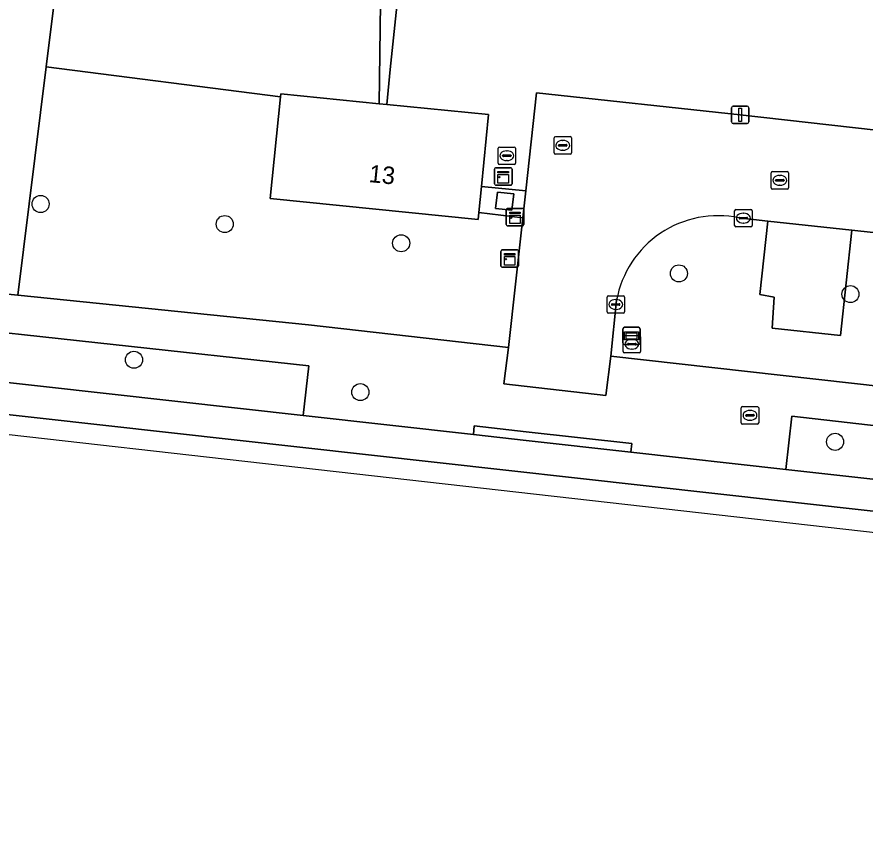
# Model space of a CAD drawing. Extents: x 162510 to 163918, y 388494 to 389774.
# Drawn here: x 162970.81 to 163019.44, y 388523.13 to 388570.84 of the extents above; entities that cross this region are included whole.
import ezdxf

# ---------------------------------------------------------------- set-up
doc = ezdxf.new("R2010")
doc.units = 0
for name, color, linetype in [('IMGEO_Berm_groen', 7, 'Continuous'), ('IMGEO_Boom', 7, 'Continuous'), ('IMGEO_Brandkraan', 7, 'Continuous'), ('IMGEO_Erf', 7, 'Continuous'), ('IMGEO_Groenvoorziening', 7, 'Continuous'), ('IMGEO_Hek', 7, 'Continuous'), ('IMGEO_Kast', 7, 'Continuous'), ('IMGEO_Kolk', 7, 'Continuous'), ('IMGEO_Lage_trafo', 7, 'Continuous'), ('IMGEO_Lichtmast', 7, 'Continuous'), ('IMGEO_Loofbos', 7, 'Continuous'), ('IMGEO_Pand', 7, 'Continuous'), ('IMGEO_Pand_nummerreeks', 7, 'Continuous'), ('IMGEO_Rijbaan_lokaal_gesloten', 7, 'Continuous'), ('IMGEO_Rijbaan_lokaal_open', 7, 'Continuous'), ('IMGEO_Rioolput', 7, 'Continuous'), ('IMGEO_Terreindeel_open', 7, 'Continuous'), ('IMGEO_Verklikker', 7, 'Continuous'), ('IMGEO_Voetpad_onverhard', 7, 'Continuous'), ('IMGEO_Voetpad_open', 7, 'Continuous')]:
    doc.layers.add(name, color=color, linetype=linetype)

msp = doc.modelspace()

# ---------------------------------------------------------------- linework, layer by layer
at = {"layer": 'IMGEO_Berm_groen'}
msp.add_lwpolyline([(163015.252, 388547.952), (163014.91, 388544.896), (163040.394, 388542.064), (163040.636, 388545.038)], close=True, dxfattribs=at)
at = {"layer": 'IMGEO_Boom'}
for centre in [(162972.163, 388560.113), (162982.721, 388558.962), (162992.839, 388557.86), (163008.769, 388556.133), (163018.606, 388554.944), (162977.517, 388551.18), (162990.498, 388549.326), (163017.725, 388546.476)]:
    msp.add_circle(centre, 0.489, dxfattribs=at)
at = {"layer": 'IMGEO_Brandkraan'}
for p, q in [((163005.57, 388551.648), (163005.57, 388552.5)), ((163005.645, 388552.574), (163006.497, 388552.574)), ((163005.872, 388552.117), (163006.27, 388552.117)), ((163006.058, 388552.354), (163006.083, 388552.354)), ((163006.571, 388552.5), (163006.571, 388551.648)), ((163005.829, 388552.068), (163005.829, 388552.08)), ((163006.267, 388552.031), (163005.869, 388552.031)), ((163006.081, 388551.794), (163006.056, 388551.794)), ((163006.313, 388552.08), (163006.313, 388552.068)), ((163006.497, 388551.574), (163005.645, 388551.574))]:
    msp.add_line(p, q, dxfattribs=at)
for points in [[(163005.57, 388551.648), (163005.57, 388552.5)], [(163005.645, 388552.574), (163006.497, 388552.574)], [(163006.571, 388552.5), (163006.571, 388551.648)], [(163006.497, 388551.574), (163005.645, 388551.574)]]:
    msp.add_lwpolyline(points, dxfattribs=at)
for centre, radius, start, end in [((163005.647, 388552.498), 0.0765, 91.552, 178.448), ((163005.647, 388552.498), 0.0765, 91.552, 178.448), ((163005.869, 388552.077), 0.0403, 85.8775, 175.7526), ((163006.274, 388552.079), 0.0386, 1.7309, 96.639), ((163006.495, 388552.498), 0.0765, 1.552, 88.448), ((163006.495, 388552.498), 0.0765, 1.552, 88.448), ((163005.647, 388551.65), 0.0765, 181.552, 268.448), ((163005.647, 388551.65), 0.0765, 181.552, 268.448), ((163005.866, 388552.067), 0.0366, 178.938, 274.7102), ((163006.27, 388552.074), 0.043, 264.8664, 352.4533), ((163006.495, 388551.65), 0.0765, 271.552, 358.448), ((163006.495, 388551.65), 0.0765, 271.552, 358.448)]:
    msp.add_arc(centre, radius, start, end, dxfattribs=at)
for centre, major_axis, ratio, start_param, end_param in [((163006.057, 388552.074), (-0.387, 0.002), 0.722429, 4.712389, 7.853982), ((163006.082, 388552.074), (-0.39, 0.002), 0.717154, 1.570796, 4.712389)]:
    msp.add_ellipse(centre, major_axis=major_axis, ratio=ratio, start_param=start_param, end_param=end_param, dxfattribs=at)
at = {"layer": 'IMGEO_Erf'}
msp.add_lwpolyline([(162992.946, 388574.941), (162992.203, 388567.817), (162992.026, 388565.819), (162997.858, 388565.235), (162997.448, 388561.109), (162999.987, 388560.86), (163000.607, 388566.496), (163012.283, 388565.224), (163023.98, 388563.913)], dxfattribs=at)
at = {"layer": 'IMGEO_Groenvoorziening'}
for points in [[(162992.946, 388574.941), (162992.355, 388574.994), (162992.829, 388580.29), (162993.498, 388580.23), (162993.73, 388582.932), (162994.196, 388586.945), (162994.478, 388589.486), (163002.555, 388588.59), (163003.829, 388588.448), (163004.733, 388595.939), (163002.79, 388596.108), (163000, 388596.356), (162992.929, 388596.983), (162991.826, 388584.623), (162991.571, 388565.865), (162992.026, 388565.819), (162992.203, 388567.817)], [(162999.817, 388559.316), (162997.301, 388559.633), (162997.261, 388559.233), (162985.319, 388560.432), (162985.926, 388566.254), (162972.488, 388567.987), (162970.86, 388554.877), (162987.529, 388553.178), (162998.998, 388551.886)], [(162987.228, 388547.98), (162987.546, 388550.825), (162965.086, 388553.284), (162964.782, 388550.488)]]:
    msp.add_lwpolyline(points, close=True, dxfattribs=at)
for points in [[(163047.561, 388555.463), (163018.69, 388558.618), (163018.036, 388552.566), (163014.124, 388552.987), (163014.233, 388554.771), (163013.404, 388554.928), (163013.862, 388559.137), (163012.22, 388559.314)], [(163005.197, 388554.592), (163004.856, 388551.379), (163026.503, 388548.968), (163052.421, 388546.115), (163052.668, 388548.774)]]:
    msp.add_lwpolyline(points, dxfattribs=at)
msp.add_arc((163011.007, 388553.534), 5.906, 78.1511, 169.6797, dxfattribs=at)
at = {"layer": 'IMGEO_Hek'}
for points in [[(163005.069, 388617.81), (163001.65, 388618.175), (163000, 388618.351), (162979.016, 388620.588), (162976.424, 388599.705), (162974.828, 388586.841), (162972.488, 388567.987)], [(162972.488, 388567.987), (162970.86, 388554.877)]]:
    msp.add_lwpolyline(points, dxfattribs=at)
at = {"layer": 'IMGEO_Kast'}
for p, q in [((162998.198, 388561.264), (162998.198, 388562.105)), ((162998.198, 388562.105), (162998.198, 388561.264)), ((162998.273, 388562.189), (162999.114, 388562.189)), ((162999.114, 388562.189), (162998.273, 388562.189)), ((162999.198, 388562.114), (162999.198, 388561.273)), ((162999.198, 388561.273), (162999.198, 388562.114)), ((162999.123, 388561.189), (162998.282, 388561.189)), ((162998.282, 388561.189), (162999.123, 388561.189)), ((162998.868, 388558.936), (162998.868, 388559.777)), ((162998.868, 388559.777), (162998.868, 388558.936)), ((162998.943, 388559.861), (162999.784, 388559.861)), ((162999.784, 388559.861), (162998.943, 388559.861)), ((162999.868, 388559.786), (162999.868, 388558.945)), ((162999.868, 388558.945), (162999.868, 388559.786)), ((162999.793, 388558.861), (162998.952, 388558.861)), ((162998.952, 388558.861), (162999.793, 388558.861)), ((162998.638, 388557.482), (162999.479, 388557.482)), ((162999.479, 388557.482), (162998.638, 388557.482)), ((162998.563, 388556.557), (162998.563, 388557.398)), ((162998.563, 388557.398), (162998.563, 388556.557)), ((162999.563, 388557.407), (162999.563, 388556.566)), ((162999.563, 388556.566), (162999.563, 388557.407)), ((162999.488, 388556.482), (162998.647, 388556.482)), ((162998.647, 388556.482), (162999.488, 388556.482))]:
    msp.add_line(p, q, dxfattribs=at)
for points in [[(162998.393, 388561.979), (162998.993, 388561.979), (162998.993, 388561.894), (162998.393, 388561.894), (162998.393, 388561.979)], [(162998.393, 388561.804), (162998.993, 388561.804), (162998.993, 388561.315), (162998.393, 388561.315), (162998.393, 388561.804)], [(162999.063, 388559.651), (162999.663, 388559.651), (162999.663, 388559.566), (162999.063, 388559.566), (162999.063, 388559.651)], [(162999.063, 388559.476), (162999.663, 388559.476), (162999.663, 388558.987), (162999.063, 388558.987), (162999.063, 388559.476)], [(162998.758, 388557.272), (162999.358, 388557.272), (162999.358, 388557.187), (162998.758, 388557.187), (162998.758, 388557.272)], [(162998.758, 388557.097), (162999.358, 388557.097), (162999.358, 388556.608), (162998.758, 388556.608), (162998.758, 388557.097)]]:
    msp.add_lwpolyline(points, dxfattribs=at)
for centre in [(162998.477, 388561.653), (162999.147, 388559.325), (162998.842, 388556.946)]:
    msp.add_circle(centre, 0.0377, dxfattribs=at)
for centre, start, end in [((162998.276, 388562.111), 92.4484, 184.2845), ((162998.276, 388562.111), 92.4484, 184.2845), ((162999.12, 388562.111), 2.4484, 94.2845), ((162999.12, 388562.111), 2.4484, 94.2845), ((162998.276, 388561.267), 182.4484, 274.2845), ((162998.276, 388561.267), 182.4484, 274.2845), ((162999.12, 388561.267), 272.4484, 4.2845), ((162999.12, 388561.267), 272.4484, 4.2845), ((162998.946, 388559.783), 92.4484, 184.2845), ((162998.946, 388559.783), 92.4484, 184.2845), ((162999.79, 388559.783), 2.4484, 94.2845), ((162999.79, 388559.783), 2.4484, 94.2845), ((162998.946, 388558.939), 182.4484, 274.2845), ((162998.946, 388558.939), 182.4484, 274.2845), ((162999.79, 388558.939), 272.4484, 4.2845), ((162999.79, 388558.939), 272.4484, 4.2845), ((162998.641, 388557.404), 92.4484, 184.2845), ((162998.641, 388557.404), 92.4484, 184.2845), ((162999.485, 388557.404), 2.4484, 94.2845), ((162999.485, 388557.404), 2.4484, 94.2845), ((162998.641, 388556.56), 182.4484, 274.2845), ((162998.641, 388556.56), 182.4484, 274.2845), ((162999.485, 388556.56), 272.4484, 4.2845), ((162999.485, 388556.56), 272.4484, 4.2845)]:
    msp.add_arc(centre, 0.0779, start, end, dxfattribs=at)
at = {"layer": 'IMGEO_Kolk'}
for p, q in [((163011.965, 388558.876), (163011.965, 388559.728)), ((163012.04, 388559.802), (163012.892, 388559.802)), ((163012.453, 388559.582), (163012.478, 388559.582)), ((163012.966, 388559.728), (163012.966, 388558.876)), ((163012.224, 388559.296), (163012.224, 388559.308)), ((163012.662, 388559.259), (163012.264, 388559.259)), ((163012.267, 388559.345), (163012.665, 388559.345)), ((163012.476, 388559.022), (163012.451, 388559.022)), ((163012.708, 388559.308), (163012.708, 388559.296)), ((163012.892, 388558.802), (163012.04, 388558.802)), ((163004.648, 388553.926), (163004.648, 388554.778)), ((163004.723, 388554.852), (163005.575, 388554.852)), ((163005.136, 388554.632), (163005.161, 388554.632)), ((163005.649, 388554.778), (163005.649, 388553.926)), ((163004.907, 388554.346), (163004.907, 388554.358)), ((163005.345, 388554.309), (163004.947, 388554.309)), ((163004.95, 388554.395), (163005.348, 388554.395)), ((163005.159, 388554.072), (163005.134, 388554.072)), ((163005.391, 388554.358), (163005.391, 388554.346)), ((163005.575, 388553.852), (163004.723, 388553.852))]:
    msp.add_line(p, q, dxfattribs=at)
for points in [[(163011.965, 388558.876), (163011.965, 388559.728)], [(163012.04, 388559.802), (163012.892, 388559.802)], [(163012.966, 388559.728), (163012.966, 388558.876)], [(163012.892, 388558.802), (163012.04, 388558.802)], [(163004.648, 388553.926), (163004.648, 388554.778)], [(163004.723, 388554.852), (163005.575, 388554.852)], [(163005.649, 388554.778), (163005.649, 388553.926)], [(163005.575, 388553.852), (163004.723, 388553.852)]]:
    msp.add_lwpolyline(points, dxfattribs=at)
for centre, radius, start, end in [((163012.042, 388559.726), 0.0765, 91.552, 178.448), ((163012.042, 388559.726), 0.0765, 91.552, 178.448), ((163012.89, 388559.726), 0.0765, 1.552, 88.448), ((163012.89, 388559.726), 0.0765, 1.552, 88.448), ((163012.264, 388559.305), 0.0403, 85.8775, 175.7526), ((163012.261, 388559.295), 0.0366, 178.938, 274.7102), ((163012.665, 388559.302), 0.043, 264.8664, 352.4533), ((163012.669, 388559.307), 0.0386, 1.7309, 96.639), ((163012.042, 388558.878), 0.0765, 181.552, 268.448), ((163012.042, 388558.878), 0.0765, 181.552, 268.448), ((163012.89, 388558.878), 0.0765, 271.552, 358.448), ((163012.89, 388558.878), 0.0765, 271.552, 358.448), ((163004.725, 388554.776), 0.0765, 91.552, 178.448), ((163004.725, 388554.776), 0.0765, 91.552, 178.448), ((163005.573, 388554.776), 0.0765, 1.552, 88.448), ((163005.573, 388554.776), 0.0765, 1.552, 88.448), ((163004.947, 388554.355), 0.0403, 85.8775, 175.7526), ((163004.944, 388554.345), 0.0366, 178.938, 274.7102), ((163005.348, 388554.352), 0.043, 264.8664, 352.4533), ((163005.352, 388554.357), 0.0386, 1.7309, 96.639), ((163004.725, 388553.928), 0.0765, 181.552, 268.448), ((163004.725, 388553.928), 0.0765, 181.552, 268.448), ((163005.573, 388553.928), 0.0765, 271.552, 358.448), ((163005.573, 388553.928), 0.0765, 271.552, 358.448)]:
    msp.add_arc(centre, radius, start, end, dxfattribs=at)
for centre, major_axis, ratio, start_param, end_param in [((163012.452, 388559.302), (-0.387, 0.002), 0.722429, 4.712389, 7.853982), ((163012.477, 388559.302), (-0.39, 0.002), 0.717154, 1.570796, 4.712389), ((163005.135, 388554.352), (-0.387, 0.002), 0.722429, 4.712389, 7.853982), ((163005.16, 388554.352), (-0.39, 0.002), 0.717154, 1.570796, 4.712389)]:
    msp.add_ellipse(centre, major_axis=major_axis, ratio=ratio, start_param=start_param, end_param=end_param, dxfattribs=at)
at = {"layer": 'IMGEO_Lage_trafo'}
msp.add_lwpolyline([(162999.3, 388560.693), (162998.36, 388560.799), (162998.254, 388559.859), (162999.194, 388559.753)], close=True, dxfattribs=at)
at = {"layer": 'IMGEO_Lichtmast'}
for p, q in [((163011.788, 388564.824), (163011.788, 388565.624)), ((163011.788, 388565.624), (163011.788, 388564.824)), ((163011.888, 388565.724), (163012.678, 388565.724)), ((163012.678, 388565.724), (163011.888, 388565.724)), ((163012.778, 388565.624), (163012.778, 388564.824)), ((163012.778, 388564.824), (163012.778, 388565.624)), ((163012.678, 388564.724), (163011.888, 388564.724)), ((163011.888, 388564.724), (163012.678, 388564.724))]:
    msp.add_line(p, q, dxfattribs=at)
msp.add_lwpolyline([(163012.208, 388565.599), (163012.358, 388565.599), (163012.358, 388564.849), (163012.208, 388564.849), (163012.208, 388565.599)], dxfattribs=at)
for centre, start, end in [((163011.888, 388565.624), 90, 180), ((163011.888, 388565.624), 90, 180), ((163012.678, 388565.624), 0, 90), ((163012.678, 388565.624), 360, 90), ((163011.888, 388564.824), 180, 270), ((163011.888, 388564.824), 180, 270), ((163012.678, 388564.824), 270, 0), ((163012.678, 388564.824), 270, 0)]:
    msp.add_arc(centre, 0.1, start, end, dxfattribs=at)
at = {"layer": 'IMGEO_Loofbos'}
msp.add_lwpolyline([(162992.929, 388596.983), (163000, 388596.356), (163002.79, 388596.108), (163005.069, 388617.81), (163001.65, 388618.175), (163000, 388618.351), (162979.016, 388620.588), (162976.424, 388599.705), (162974.828, 388586.841), (162972.488, 388567.987), (162985.926, 388566.254), (162985.944, 388566.429), (162991.571, 388565.865), (162991.826, 388584.623)], close=True, dxfattribs=at)
at = {"layer": 'IMGEO_Pand'}
msp.add_lwpolyline([(162997.858, 388565.235), (162992.026, 388565.819), (162991.571, 388565.865), (162985.944, 388566.429), (162985.926, 388566.254), (162985.319, 388560.432), (162997.261, 388559.233), (162997.301, 388559.633), (162997.448, 388561.109)], close=True, dxfattribs=at)
at = {"layer": 'IMGEO_Rijbaan_lokaal_gesloten'}
for points in [[(163040.394, 388542.064), (163014.91, 388544.896), (163006.017, 388545.884), (163000, 388546.554), (162996.98, 388546.89), (162987.228, 388547.98), (162964.782, 388550.488), (162957.098, 388551.346), (162948.524, 388552.307), (162920.643, 388555.418), (162911.472, 388556.441), (162909.166, 388556.698), (162908.963, 388554.88), (162948.321, 388550.488), (162948.369, 388550.483), (162964.579, 388548.669), (162987.025, 388546.161), (163014.762, 388543.071), (163031.566, 388541.204)], [(163178.982, 388523.125), (163178.758, 388523.432), (163178.09, 388524.156), (163177.403, 388524.656), (163176.288, 388525.112), (163175.638, 388525.237), (163131.035, 388530.402), (163114.004, 388532.296), (163069.219, 388537.019), (163059.674, 388538.08), (163040.29, 388540.234), (163031.566, 388541.204), (163014.762, 388543.071), (162987.025, 388546.161), (162964.579, 388548.669), (162948.369, 388550.483), (162948.321, 388550.488), (162908.963, 388554.88), (162908.848, 388553.848), (163175.64, 388523.673), (163178.982, 388523.125)]]:
    msp.add_lwpolyline(points, dxfattribs=at)
at = {"layer": 'IMGEO_Rijbaan_lokaal_open'}
for points in [[(163047.901, 388561.655), (163035.984, 388562.926), (163024.016, 388564.261), (163023.98, 388563.913), (163012.283, 388565.224), (163000.607, 388566.496), (162999.987, 388560.86), (162999.817, 388559.316), (162998.998, 388551.886), (162998.719, 388549.807), (163004.579, 388549.125), (163004.856, 388551.379), (163005.197, 388554.592)], [(163012.22, 388559.314), (163013.862, 388559.137), (163018.69, 388558.618), (163047.561, 388555.463)]]:
    msp.add_lwpolyline(points, dxfattribs=at)
msp.add_arc((163011.007, 388553.534), 5.906, 78.1511, 169.6797, dxfattribs=at)
at = {"layer": 'IMGEO_Rioolput'}
for p, q in [((163001.607, 388563.05), (163001.607, 388563.902)), ((163001.682, 388563.976), (163002.534, 388563.976)), ((163002.608, 388563.902), (163002.608, 388563.05)), ((162998.401, 388562.454), (162998.401, 388563.306)), ((162998.476, 388563.38), (162999.328, 388563.38)), ((162999.402, 388563.306), (162999.402, 388562.454)), ((163001.866, 388563.47), (163001.866, 388563.482)), ((163002.304, 388563.433), (163001.906, 388563.433)), ((163001.909, 388563.519), (163002.307, 388563.519)), ((163002.095, 388563.756), (163002.12, 388563.756)), ((163002.35, 388563.482), (163002.35, 388563.47)), ((162998.66, 388562.874), (162998.66, 388562.886)), ((162999.098, 388562.837), (162998.7, 388562.837)), ((162998.703, 388562.923), (162999.101, 388562.923)), ((162998.889, 388563.16), (162998.914, 388563.16)), ((162999.144, 388562.886), (162999.144, 388562.874)), ((163002.534, 388562.976), (163001.682, 388562.976)), ((163002.118, 388563.196), (163002.093, 388563.196)), ((162999.328, 388562.38), (162998.476, 388562.38)), ((162998.912, 388562.6), (162998.887, 388562.6)), ((163014.054, 388561.042), (163014.054, 388561.894)), ((163014.129, 388561.968), (163014.981, 388561.968)), ((163015.055, 388561.894), (163015.055, 388561.042)), ((163014.313, 388561.462), (163014.313, 388561.474)), ((163014.751, 388561.425), (163014.353, 388561.425)), ((163014.356, 388561.511), (163014.754, 388561.511)), ((163014.542, 388561.748), (163014.567, 388561.748)), ((163014.797, 388561.474), (163014.797, 388561.462)), ((163014.981, 388560.968), (163014.129, 388560.968)), ((163014.565, 388561.188), (163014.54, 388561.188)), ((163012.345, 388547.568), (163012.345, 388548.42)), ((163012.42, 388548.494), (163013.272, 388548.494)), ((163012.833, 388548.274), (163012.858, 388548.274)), ((163013.346, 388548.42), (163013.346, 388547.568)), ((163012.604, 388547.988), (163012.604, 388548)), ((163013.042, 388547.951), (163012.644, 388547.951)), ((163012.647, 388548.037), (163013.045, 388548.037)), ((163013.088, 388548), (163013.088, 388547.988)), ((163013.272, 388547.494), (163012.42, 388547.494)), ((163012.856, 388547.714), (163012.831, 388547.714))]:
    msp.add_line(p, q, dxfattribs=at)
for points in [[(163001.607, 388563.05), (163001.607, 388563.902)], [(163001.682, 388563.976), (163002.534, 388563.976)], [(163002.608, 388563.902), (163002.608, 388563.05)], [(162998.401, 388562.454), (162998.401, 388563.306)], [(162998.476, 388563.38), (162999.328, 388563.38)], [(162999.402, 388563.306), (162999.402, 388562.454)], [(163002.534, 388562.976), (163001.682, 388562.976)], [(162999.328, 388562.38), (162998.476, 388562.38)], [(163014.054, 388561.042), (163014.054, 388561.894)], [(163014.129, 388561.968), (163014.981, 388561.968)], [(163015.055, 388561.894), (163015.055, 388561.042)], [(163014.981, 388560.968), (163014.129, 388560.968)], [(163012.345, 388547.568), (163012.345, 388548.42)], [(163012.42, 388548.494), (163013.272, 388548.494)], [(163013.346, 388548.42), (163013.346, 388547.568)], [(163013.272, 388547.494), (163012.42, 388547.494)]]:
    msp.add_lwpolyline(points, dxfattribs=at)
for centre, radius, start, end in [((163001.684, 388563.9), 0.0765, 91.552, 178.448), ((163001.684, 388563.9), 0.0765, 91.552, 178.448), ((163002.532, 388563.9), 0.0765, 1.552, 88.448), ((163002.532, 388563.9), 0.0765, 1.552, 88.448), ((162998.478, 388563.304), 0.0765, 91.552, 178.448), ((162998.478, 388563.304), 0.0765, 91.552, 178.448), ((162999.326, 388563.304), 0.0765, 1.552, 88.448), ((162999.326, 388563.304), 0.0765, 1.552, 88.448), ((163001.906, 388563.479), 0.0403, 85.8775, 175.7526), ((163001.903, 388563.469), 0.0366, 178.938, 274.7102), ((163002.307, 388563.476), 0.043, 264.8664, 352.4533), ((163002.311, 388563.481), 0.0386, 1.7309, 96.639), ((162998.7, 388562.883), 0.0403, 85.8775, 175.7526), ((162998.697, 388562.873), 0.0366, 178.938, 274.7102), ((162999.101, 388562.88), 0.043, 264.8664, 352.4533), ((162999.105, 388562.885), 0.0386, 1.7309, 96.639), ((163001.684, 388563.052), 0.0765, 181.552, 268.448), ((163001.684, 388563.052), 0.0765, 181.552, 268.448), ((163002.532, 388563.052), 0.0765, 271.552, 358.448), ((163002.532, 388563.052), 0.0765, 271.552, 358.448), ((162998.478, 388562.456), 0.0765, 181.552, 268.448), ((162998.478, 388562.456), 0.0765, 181.552, 268.448), ((162999.326, 388562.456), 0.0765, 271.552, 358.448), ((162999.326, 388562.456), 0.0765, 271.552, 358.448), ((163014.131, 388561.892), 0.0765, 91.552, 178.448), ((163014.131, 388561.892), 0.0765, 91.552, 178.448), ((163014.979, 388561.892), 0.0765, 1.552, 88.448), ((163014.979, 388561.892), 0.0765, 1.552, 88.448), ((163014.353, 388561.471), 0.0403, 85.8775, 175.7526), ((163014.35, 388561.461), 0.0366, 178.938, 274.7102), ((163014.754, 388561.468), 0.043, 264.8664, 352.4533), ((163014.758, 388561.473), 0.0386, 1.7309, 96.639), ((163014.131, 388561.044), 0.0765, 181.552, 268.448), ((163014.131, 388561.044), 0.0765, 181.552, 268.448), ((163014.979, 388561.044), 0.0765, 271.552, 358.448), ((163014.979, 388561.044), 0.0765, 271.552, 358.448), ((163012.422, 388548.418), 0.0765, 91.552, 178.448), ((163012.422, 388548.418), 0.0765, 91.552, 178.448), ((163013.27, 388548.418), 0.0765, 1.552, 88.448), ((163013.27, 388548.418), 0.0765, 1.552, 88.448), ((163012.644, 388547.997), 0.0403, 85.8775, 175.7526), ((163012.641, 388547.987), 0.0366, 178.938, 274.7102), ((163013.045, 388547.994), 0.043, 264.8664, 352.4533), ((163013.049, 388547.999), 0.0386, 1.7309, 96.639), ((163012.422, 388547.57), 0.0765, 181.552, 268.448), ((163012.422, 388547.57), 0.0765, 181.552, 268.448), ((163013.27, 388547.57), 0.0765, 271.552, 358.448), ((163013.27, 388547.57), 0.0765, 271.552, 358.448)]:
    msp.add_arc(centre, radius, start, end, dxfattribs=at)
for centre, major_axis, ratio, start_param, end_param in [((163002.094, 388563.476), (-0.387, 0.002), 0.722429, 4.712389, 7.853982), ((163002.119, 388563.476), (-0.39, 0.002), 0.717154, 1.570796, 4.712389), ((162998.888, 388562.88), (-0.387, 0.002), 0.722429, 4.712389, 7.853982), ((162998.913, 388562.88), (-0.39, 0.002), 0.717154, 1.570796, 4.712389), ((163014.541, 388561.468), (-0.387, 0.002), 0.722429, 4.712389, 7.853982), ((163014.566, 388561.468), (-0.39, 0.002), 0.717154, 1.570796, 4.712389), ((163012.832, 388547.994), (-0.387, 0.002), 0.722429, 4.712389, 7.853982), ((163012.857, 388547.994), (-0.39, 0.002), 0.717154, 1.570796, 4.712389)]:
    msp.add_ellipse(centre, major_axis=major_axis, ratio=ratio, start_param=start_param, end_param=end_param, dxfattribs=at)
at = {"layer": 'IMGEO_Terreindeel_open'}
for points in [[(162999.987, 388560.86), (162997.448, 388561.109), (162997.301, 388559.633), (162999.817, 388559.316)], [(162999.194, 388559.753), (162998.254, 388559.859), (162998.36, 388560.799), (162999.3, 388560.693)]]:
    msp.add_lwpolyline(points, close=True, dxfattribs=at)
at = {"layer": 'IMGEO_Verklikker'}
for p, q in [((163005.554, 388552.147), (163005.554, 388552.947)), ((163005.554, 388552.947), (163005.554, 388552.147)), ((163005.654, 388553.047), (163006.444, 388553.047)), ((163006.444, 388553.047), (163005.654, 388553.047)), ((163006.544, 388552.947), (163006.544, 388552.147)), ((163006.544, 388552.147), (163006.544, 388552.947)), ((163006.444, 388552.047), (163005.654, 388552.047)), ((163005.654, 388552.047), (163006.444, 388552.047))]:
    msp.add_line(p, q, dxfattribs=at)
for points in [[(163005.655, 388552.779), (163006.443, 388552.779), (163006.443, 388552.315), (163005.655, 388552.315), (163005.655, 388552.779)], [(163005.72, 388552.714), (163005.72, 388552.38), (163006.378, 388552.38), (163006.378, 388552.714), (163005.72, 388552.714)]]:
    msp.add_lwpolyline(points, dxfattribs=at)
for centre, start, end in [((163005.654, 388552.947), 90, 180), ((163005.654, 388552.947), 90, 180), ((163006.444, 388552.947), 0, 90), ((163006.444, 388552.947), 360, 90), ((163005.654, 388552.147), 180, 270), ((163005.654, 388552.147), 180, 270), ((163006.444, 388552.147), 270, 0), ((163006.444, 388552.147), 270, 0)]:
    msp.add_arc(centre, 0.1, start, end, dxfattribs=at)
at = {"layer": 'IMGEO_Voetpad_onverhard'}
msp.add_lwpolyline([(163066.203, 388615.891), (162973.501, 388626.071), (162971.679, 388611.418), (162968.591, 388586.594), (162965.32, 388555.442), (162970.86, 388554.877), (162972.488, 388567.987), (162974.828, 388586.841), (162976.424, 388599.705), (162979.016, 388620.588), (163000, 388618.351), (163001.65, 388618.175), (163005.069, 388617.81), (163005.707, 388617.745), (163005.799, 388618.536), (163092.645, 388608.787)], dxfattribs=at)
at = {"layer": 'IMGEO_Voetpad_open'}
for points in [[(163018.69, 388558.618), (163013.862, 388559.137), (163013.404, 388554.928), (163014.233, 388554.771), (163014.124, 388552.987), (163018.036, 388552.566)], [(163006.017, 388545.884), (163006.072, 388546.38), (163000, 388547.056), (162997.035, 388547.386), (162996.98, 388546.89), (163000, 388546.554)]]:
    msp.add_lwpolyline(points, close=True, dxfattribs=at)
for points in [[(163026.503, 388548.968), (163004.856, 388551.379), (163004.579, 388549.125), (162998.719, 388549.807), (162998.998, 388551.886), (162987.529, 388553.178), (162970.86, 388554.877), (162965.32, 388555.442)], [(162965.086, 388553.284), (162987.546, 388550.825), (162987.228, 388547.98), (162996.98, 388546.89), (162997.035, 388547.386), (163000, 388547.056), (163006.072, 388546.38), (163006.017, 388545.884), (163014.91, 388544.896), (163015.252, 388547.952), (163040.636, 388545.038)]]:
    msp.add_lwpolyline(points, dxfattribs=at)

# ---------------------------------------------------------------- texts
at = {"layer": 'IMGEO_Pand_nummerreeks'}
msp.add_text('13', height=1, rotation=354.2647, dxfattribs=at).set_placement((162990.957, 388561.374))

doc.saveas('drawing.dxf')
